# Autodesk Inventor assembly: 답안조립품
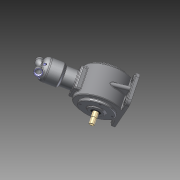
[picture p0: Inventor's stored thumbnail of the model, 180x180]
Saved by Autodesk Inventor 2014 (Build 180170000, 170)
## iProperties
Created: 2015-06
Part Number: 답안조립품
Document SubType Name: Assembly
Designer: user
Author: user
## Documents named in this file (15)
- C:\Users\user\Desktop\450606v1037\답안조립품.iam
- C:\Users\user\Desktop\450606v1037\본체.ipt
- C:\Users\user\Desktop\450606v1037\베어링 6204.ipt
- C:\Users\user\Desktop\450606v1037\메인 크랭크 축-구동부.ipt
- C:\Users\user\Desktop\450606v1037\크랭크 서브축.ipt
- C:\Users\user\Desktop\450606v1037\커넥팅 로드.ipt
- C:\Users\user\Desktop\450606v1037\베어링 NA 4902.ipt
- C:\Users\user\Desktop\450606v1037\피스톤 핀.ipt
- C:\Users\user\Desktop\450606v1037\피스톤.ipt
- C:\Users\user\Desktop\450606v1037\실린더.ipt
- C:\Users\user\Desktop\450606v1037\실린더헤드.ipt
- C:\Users\user\Desktop\450606v1037\오일실.ipt
- C:\Users\user\Desktop\450606v1037\메인커버.ipt
- C:\Users\user\Desktop\450606v1037\M4x0.7.ipt
- C:\Users\user\Desktop\450606v1037\M5x0.8.ipt
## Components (10 placed, 4 different names)
1. 피스톤 핀:1 — Mate:1, Mate:2, Mate:3
2. 피스톤:1 — Tangent:1, Mate:1, Mate:2, Mate:4, Mate:5
3. M5x0.8:1 — Insert:12
4. M5x0.8:2
5. M5x0.8:3
6. M5x0.8:4
7. M4x0.7:1 — Insert:13
8. M4x0.7:2
9. M4x0.7:3
10. M4x0.7:4
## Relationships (8: Mate 5, Insert 2, Tangent 1)
- Tangent:1: 피스톤:1
- Mate:1: 피스톤 핀:1 ↔ 피스톤:1
- Mate:2: 피스톤 핀:1 ↔ 피스톤:1
- Mate:3: 피스톤 핀:1
- Mate:4: 피스톤:1
- Mate:5: 피스톤:1
- Insert:12: M5x0.8:1
- Insert:13: M4x0.7:1
